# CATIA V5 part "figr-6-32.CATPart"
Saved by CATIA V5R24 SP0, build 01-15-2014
Part number: Part1
Bounding box of the stored display mesh (mm): x -36 to 36, y -66.608 to 66.608, z -13.545 to 13.545
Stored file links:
  D:\KAVITA\CATIA V5-6R2014 Project_ Kavita\CATIA V5-6R2014_partfiles\Partfiles\c06_catia_v5-6r2014_prt\figr-6-32.CATPart
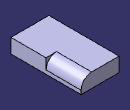
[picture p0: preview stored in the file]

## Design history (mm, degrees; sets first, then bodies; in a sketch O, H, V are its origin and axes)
Body1 (main body)
  Sketch1 on yz-plane, origin (0, 0, 0), H (0, 1, 0), V (0, 0, 1)
    line L1 (-66.6077, 13.5449) -> (66.6077, 13.5449)
    line L2 (66.6077, 13.5449) -> (66.6077, -13.5449)
    line L3 (66.6077, -13.5449) -> (-66.6077, -13.5449)
    line L4 (-66.6077, -13.5449) -> (-66.6077, 13.5449)
    axis line L5 (66.6077, -13.5449) -> (-66.6077, 13.5449)
    horizontal: L1 H, L3 H
    vertical: L2 V, L4 V
    midpoint: O L5
  Pad1: profile Sketch1, direction (1, 0, 0), length 36, mirrored extent
  Fillet1: radius 20, on edge [face of Pad1 | face of Pad1]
